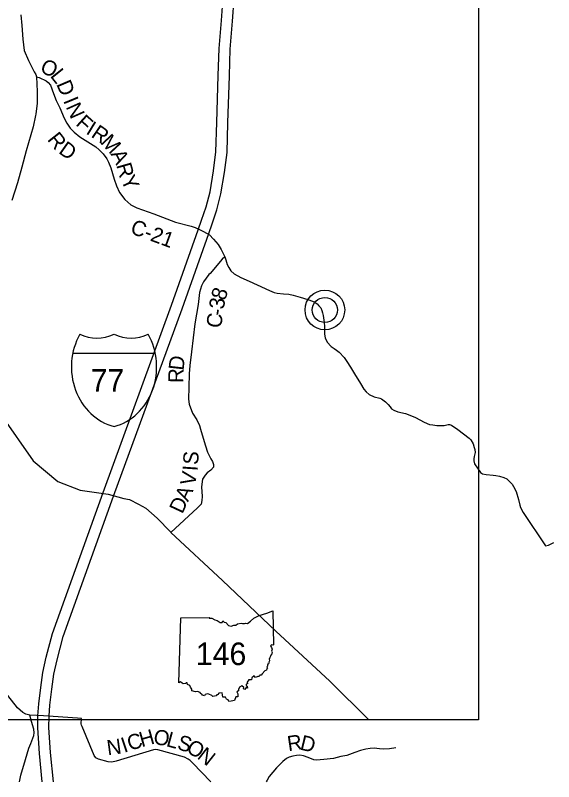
# Model space of a CAD drawing. Extents: x -452339 to 6403467, y -1 to 1814750.
# Drawn here: x 74983 to 96309, y 1599652 to 1629997 of the extents above; entities that cross this region are included whole.
import ezdxf

# ---------------------------------------------------------------- set-up
doc = ezdxf.new("R2010")
doc.units = 0
for name, color, linetype in [('Default', 7, 'Continuous'), ('GM_X_County', 7, 'Continuous'), ('GM_X_County_Road', 7, 'Continuous'), ('GM_X_County_Road_Text', 7, 'Continuous'), ('GM_X_Minor_Lake_Text', 7, 'Continuous')]:
    doc.layers.add(name, color=color, linetype=linetype)

msp = doc.modelspace()

# ---------------------------------------------------------------- linework, layer by layer
at = {"layer": 'Default'}
for p, q in [((93325, 1641599), (93325, 1602105)), ((81454, 1603560), (81537, 1606142)), ((93325, 1602105), (53831, 1602105))]:
    msp.add_line(p, q, dxfattribs=at)
for points in [[(75823, 1627563), (75923, 1627530), (76201, 1627399), (76280, 1627342), (76375, 1627233), (76495, 1626904), (76604, 1626622), (76745, 1626329), (76913, 1625923), (77018, 1625722), (77152, 1625532), (77310, 1625367), (77544, 1625184), (77956, 1624928), (78171, 1624790), (78301, 1624672), (78459, 1624507), (78605, 1624321), (78679, 1624180), (78765, 1623963), (78896, 1623510), (78985, 1623252), (79114, 1622983), (79315, 1622709), (79557, 1622494), (79799, 1622376), (80467, 1622133), (81330, 1621812), (81951, 1621650), (82111, 1621597), (82254, 1621531), (82439, 1621436), (82670, 1621299), (82836, 1621137), (83014, 1620927), (83140, 1620722), (83277, 1620440)], [(83277, 1620440), (83180, 1620341), (82695, 1619777), (82655, 1619731)], [(83277, 1620440), (83323, 1620312), (83381, 1620135), (83436, 1620006), (83514, 1619874), (83653, 1619756), (83911, 1619622), (84241, 1619466), (84567, 1619327), (85048, 1619102), (85238, 1619020), (85354, 1618991), (85605, 1618964), (85816, 1618950), (85996, 1618921), (86263, 1618842), (86573, 1618751), (86756, 1618673), (86863, 1618624), (86936, 1618577), (87008, 1618500), (87089, 1618414), (87121, 1618309), (87151, 1618215)], [(82655, 1619731), (82654, 1619730), (82537, 1619595), (82432, 1619444), (82355, 1619288), (82280, 1619025), (82223, 1618541), (82095, 1617780), (81962, 1616676), (81895, 1616134), (81865, 1615805), (81858, 1615268), (81846, 1614799), (81874, 1614604), (82000, 1614249), (82168, 1613984), (82276, 1613754), (82323, 1613606), (82391, 1613387), (82518, 1612949), (82594, 1612702), (82727, 1612440), (82797, 1612333), (82834, 1612209), (82833, 1612110), (82727, 1611987), (82581, 1611885), (82498, 1611795), (82401, 1611637), (82362, 1611324), (82385, 1610948), (82376, 1610780), (82350, 1610643), (82201, 1610496), (81139, 1609525)], [(87151, 1618215), (87176, 1618108), (87217, 1617836), (87236, 1617680), (87227, 1617476), (87225, 1617376), (87255, 1617232), (87334, 1617061), (87501, 1616884), (87611, 1616798), (87708, 1616739), (87809, 1616653), (88005, 1616444), (88116, 1616286), (88256, 1616060), (88424, 1615799), (88651, 1615423), (88790, 1615197), (88884, 1615090), (89002, 1614988), (89200, 1614896), (89420, 1614844), (89493, 1614809), (89651, 1614695), (89757, 1614581), (89826, 1614494), (89884, 1614415), (89973, 1614361), (90130, 1614300), (90435, 1614229), (90544, 1614187), (90842, 1614072), (91185, 1613886), (91394, 1613798), (91518, 1613784), (91675, 1613751), (91967, 1613756), (92130, 1613791), (92186, 1613800), (92267, 1613765), (92506, 1613593), (92967, 1613253), (93028, 1613190), (93115, 1613023), (93166, 1612884), (93191, 1612800), (93193, 1612688), (93156, 1612523), (93141, 1612435), (93147, 1612351), (93177, 1612235), (93407, 1611891), (93492, 1611837), (93636, 1611811), (93909, 1611788), (94013, 1611770), (94161, 1611748), (94338, 1611696), (94459, 1611642), (94561, 1611539), (94663, 1611433), (94724, 1611346), (94819, 1611147), (94921, 1610829), (94965, 1610601), (94995, 1610506), (95094, 1610315), (95991, 1608986), (96104, 1609016), (96309, 1609119)], [(81537, 1606142), (82682, 1606159), (82664, 1606128), (82772, 1606122), (82887, 1606066), (82984, 1606032), (83102, 1605950), (83173, 1605950), (83204, 1606018), (83258, 1605966), (83323, 1605956), (83434, 1605833), (83527, 1605806), (83637, 1605849), (83719, 1605855), (83779, 1605897), (83936, 1605933), (83981, 1605911), (84064, 1605916), (84106, 1605932), (84179, 1605918), (84305, 1606012), (84437, 1606122), (84640, 1606227), (84941, 1606325), (85180, 1606414), (85215, 1605074)], [(85215, 1605074), (85180, 1605055), (85125, 1605064), (85088, 1605027), (85134, 1604964), (85155, 1604898), (85136, 1604825), (85155, 1604765), (85142, 1604714), (85108, 1604663), (85096, 1604616), (85066, 1604566), (85068, 1604537), (85041, 1604516), (85046, 1604431), (85032, 1604385), (85037, 1604345), (84991, 1604335), (85002, 1604301), (84973, 1604275), (84979, 1604232), (84946, 1604203), (84978, 1604147), (84952, 1604129), (84931, 1604061), (84873, 1604047), (84757, 1603922), (84716, 1603875), (84670, 1603863), (84644, 1603815), (84588, 1603815), (84501, 1603781), (84445, 1603839), (84348, 1603769), (84337, 1603688), (84214, 1603691), (84219, 1603650), (84191, 1603638), (84167, 1603598), (84181, 1603525), (84123, 1603507), (84130, 1603465), (84167, 1603439), (84183, 1603359), (84122, 1603375), (84072, 1603307), (84020, 1603323), (84037, 1603380), (83950, 1603450), (83867, 1603395), (83824, 1603306), (83824, 1603246), (83762, 1603210), (83802, 1603127), (83794, 1603069), (83796, 1603013), (83719, 1603016), (83672, 1602867)], [(77627, 1601841), (77626, 1601842), (77605, 1601891), (77597, 1601943), (77611, 1602155), (77443, 1602170), (76099, 1602254), (75563, 1602287), (75395, 1602330), (75275, 1602385), (75069, 1602575), (74392, 1603431)], [(83672, 1602867), (83539, 1602839), (83446, 1602822), (83413, 1602889), (83347, 1602925), (83303, 1602992), (83208, 1603002), (83186, 1603095), (83175, 1603170), (83045, 1603152), (83010, 1603106), (82963, 1603093), (82937, 1603046), (82873, 1603043), (82806, 1603021), (82761, 1603066), (82651, 1603112), (82601, 1603136), (82497, 1603099), (82475, 1603056), (82393, 1603075), (82373, 1603123), (82323, 1603138), (82312, 1603189), (82205, 1603217), (82122, 1603206), (81978, 1603247), (81969, 1603315), (81919, 1603398), (81895, 1603455), (81803, 1603498), (81784, 1603566), (81755, 1603565), (81729, 1603537), (81627, 1603524), (81586, 1603552), (81529, 1603600), (81454, 1603560)], [(75143, 1599652), (75204, 1599909), (75387, 1600531), (75512, 1600977), (75595, 1601170), (75717, 1601483), (75736, 1601583), (75715, 1601727), (75625, 1602039), (75563, 1602287)], [(82724, 1599652), (82005, 1600403), (81913, 1600495), (81828, 1600546), (81680, 1600617), (80630, 1600909), (80522, 1600924), (80458, 1600916), (78974, 1600463), (78807, 1600430), (78663, 1600433), (78274, 1600538), (78222, 1600570), (78173, 1600597), (78109, 1600685), (77627, 1601841)], [(90056, 1600989), (89810, 1600957), (89554, 1600943), (89410, 1600954), (89198, 1600976), (89046, 1600971), (88862, 1600945), (88655, 1600892), (88432, 1600806), (88113, 1600695), (87873, 1600645), (87582, 1600571), (87206, 1600524), (86910, 1600502), (86810, 1600517), (86582, 1600615), (86405, 1600670), (86253, 1600697), (86125, 1600692), (85978, 1600667), (85826, 1600621), (85726, 1600568), (85575, 1600455), (85329, 1600205), (85040, 1599854), (84957, 1599717), (84921, 1599652)]]:
    msp.add_lwpolyline(points, dxfattribs=at)
for centre, major_axis, start_param, end_param in [((79384, 1616077), (0, -2422), 4.15077, 6.05619), ((78216, 1619147), (0, -1932), 5.88324, 6.683049), ((78403, 1616077), (0, -2422), 0.227007, 2.13242), ((79571, 1619148), (0, -1933), 5.883359, 6.683012)]:
    msp.add_ellipse(centre, major_axis=major_axis, ratio=0.9, start_param=start_param, end_param=end_param, dxfattribs=at)
at = {"layer": 'GM_X_County_Road'}
for points in [[(78458, 1611106), (81172, 1618520), (82232, 1621509), (82364, 1621883), (82549, 1622417), (82699, 1623014), (82840, 1623835), (82930, 1624594), (82960, 1625758), (83025, 1627609), (83057, 1628684), (83149, 1629798), (83211, 1630732), (83338, 1631537), (83625, 1632957), (83847, 1633999)], [(78871, 1610955), (81586, 1618371), (82647, 1621362), (82780, 1621738), (82971, 1622291), (83130, 1622923), (83275, 1623772), (83370, 1624562), (83400, 1625745), (83465, 1627595), (83496, 1628659), (83587, 1629766), (83649, 1630683), (83771, 1631460), (84056, 1632867), (84278, 1633907)], [(75200, 1630017), (75235, 1629588), (75279, 1629053), (75340, 1628600), (75509, 1628213), (75600, 1628029), (75733, 1627760), (75792, 1627659), (75823, 1627563), (75849, 1626986), (75853, 1626519), (75794, 1626087), (75794, 1626084)], [(75794, 1626084), (75787, 1626034), (75696, 1625580), (75415, 1624632), (75243, 1623981), (75071, 1623358), (74851, 1622670)], [(74439, 1614149), (75689, 1612357), (76671, 1611542), (77557, 1611201), (78665, 1611030), (79283, 1610868), (79509, 1610822), (79862, 1610642), (80151, 1610476), (80597, 1610085), (81124, 1609539), (81139, 1609525), (83195, 1607624), (85302, 1605610), (87437, 1603632), (87449, 1603620), (88989, 1602105)], [(76049, 1599652), (75937, 1600774), (75874, 1601789), (75879, 1602263), (75913, 1602729), (75993, 1603379), (76079, 1603980), (76207, 1604582), (76454, 1605524), (78458, 1611104)], [(76492, 1599652), (76376, 1600809), (76314, 1601800), (76319, 1602244), (76351, 1602687), (76429, 1603320), (76512, 1603903), (76636, 1604481), (76874, 1605394), (78872, 1610956)]]:
    msp.add_lwpolyline(points, dxfattribs=at)
at = {"layer": 'GM_X_County_Road_Text'}
for radius in [786, 498]:
    msp.add_circle((87246, 1618329), radius, dxfattribs=at)
at = {"layer": 'GM_X_Minor_Lake_Text'}
msp.add_line((77265, 1616622), (80527, 1616622), dxfattribs=at)

# ---------------------------------------------------------------- texts
at = {"layer": 'Default'}
for s, p in [('77', (77967, 1615095)), ('146', (82134, 1604268))]:
    msp.add_text(s, height=895.5, dxfattribs=at).set_placement(p)
at = {"layer": 'GM_X_County'}
for s, rotation, p in [('O', 333.2183, (75919, 1627785)), ('L', 308.7421, (76338, 1627590)), ('D', 293.013, (76597, 1627277)), ('I', 292.2949, (76873, 1626621)), ('N', 294.0168, (76974, 1626375)), ('F', 317.8384, (77347, 1625674)), ('I', 328.6139, (77746, 1625329)), ('R', 325.7882, (77950, 1625205)), ('R', 308.5227, (76225, 1625073)), ('M', 312.863, (78330, 1624951)), ('D', 324.605, (76663, 1624563)), ('A', 296.6433, (78748, 1624510)), ('R', 286.0151, (78974, 1624066)), ('Y', 295.5868, (79149, 1623490)), ('C-21', 339.725, (79500, 1621378)), ('8', 72.1493, (83287, 1618674)), ('3', 82.7498, (83247, 1618336)), ('-', 80.9845, (83206, 1618073)), ('C', 80.5787, (83124, 1617582)), ('D', 83.7366, (81646, 1615915)), ('R', 88.9774, (81639, 1615436)), ('S', 85.4814, (82218, 1612183)), ('V', 79.2362, (82092, 1611342)), ('I', 86.0564, (82201, 1611938)), ('A', 65.3128, (81823, 1610711)), ('D', 64.9811, (81598, 1610229)), ('H', 15.7673, (79987, 1601013)), ('O', 350.1304, (80425, 1601153)), ('L', 344.5261, (80930, 1601066)), ('N', 7.6397, (78645, 1600693)), ('I', 18.5685, (79290, 1600792)), ('C', 17.0944, (79519, 1600869)), ('S', 343.821, (81360, 1600946)), ('R', 8.3189, (85800, 1600856)), ('D', 346.0159, (86227, 1600931)), ('O', 329.9384, (81714, 1600849)), ('N', 321.8215, (82152, 1600597))]:
    msp.add_text(s, height=600, rotation=rotation, dxfattribs=at).set_placement(p)

doc.saveas('drawing.dxf')
